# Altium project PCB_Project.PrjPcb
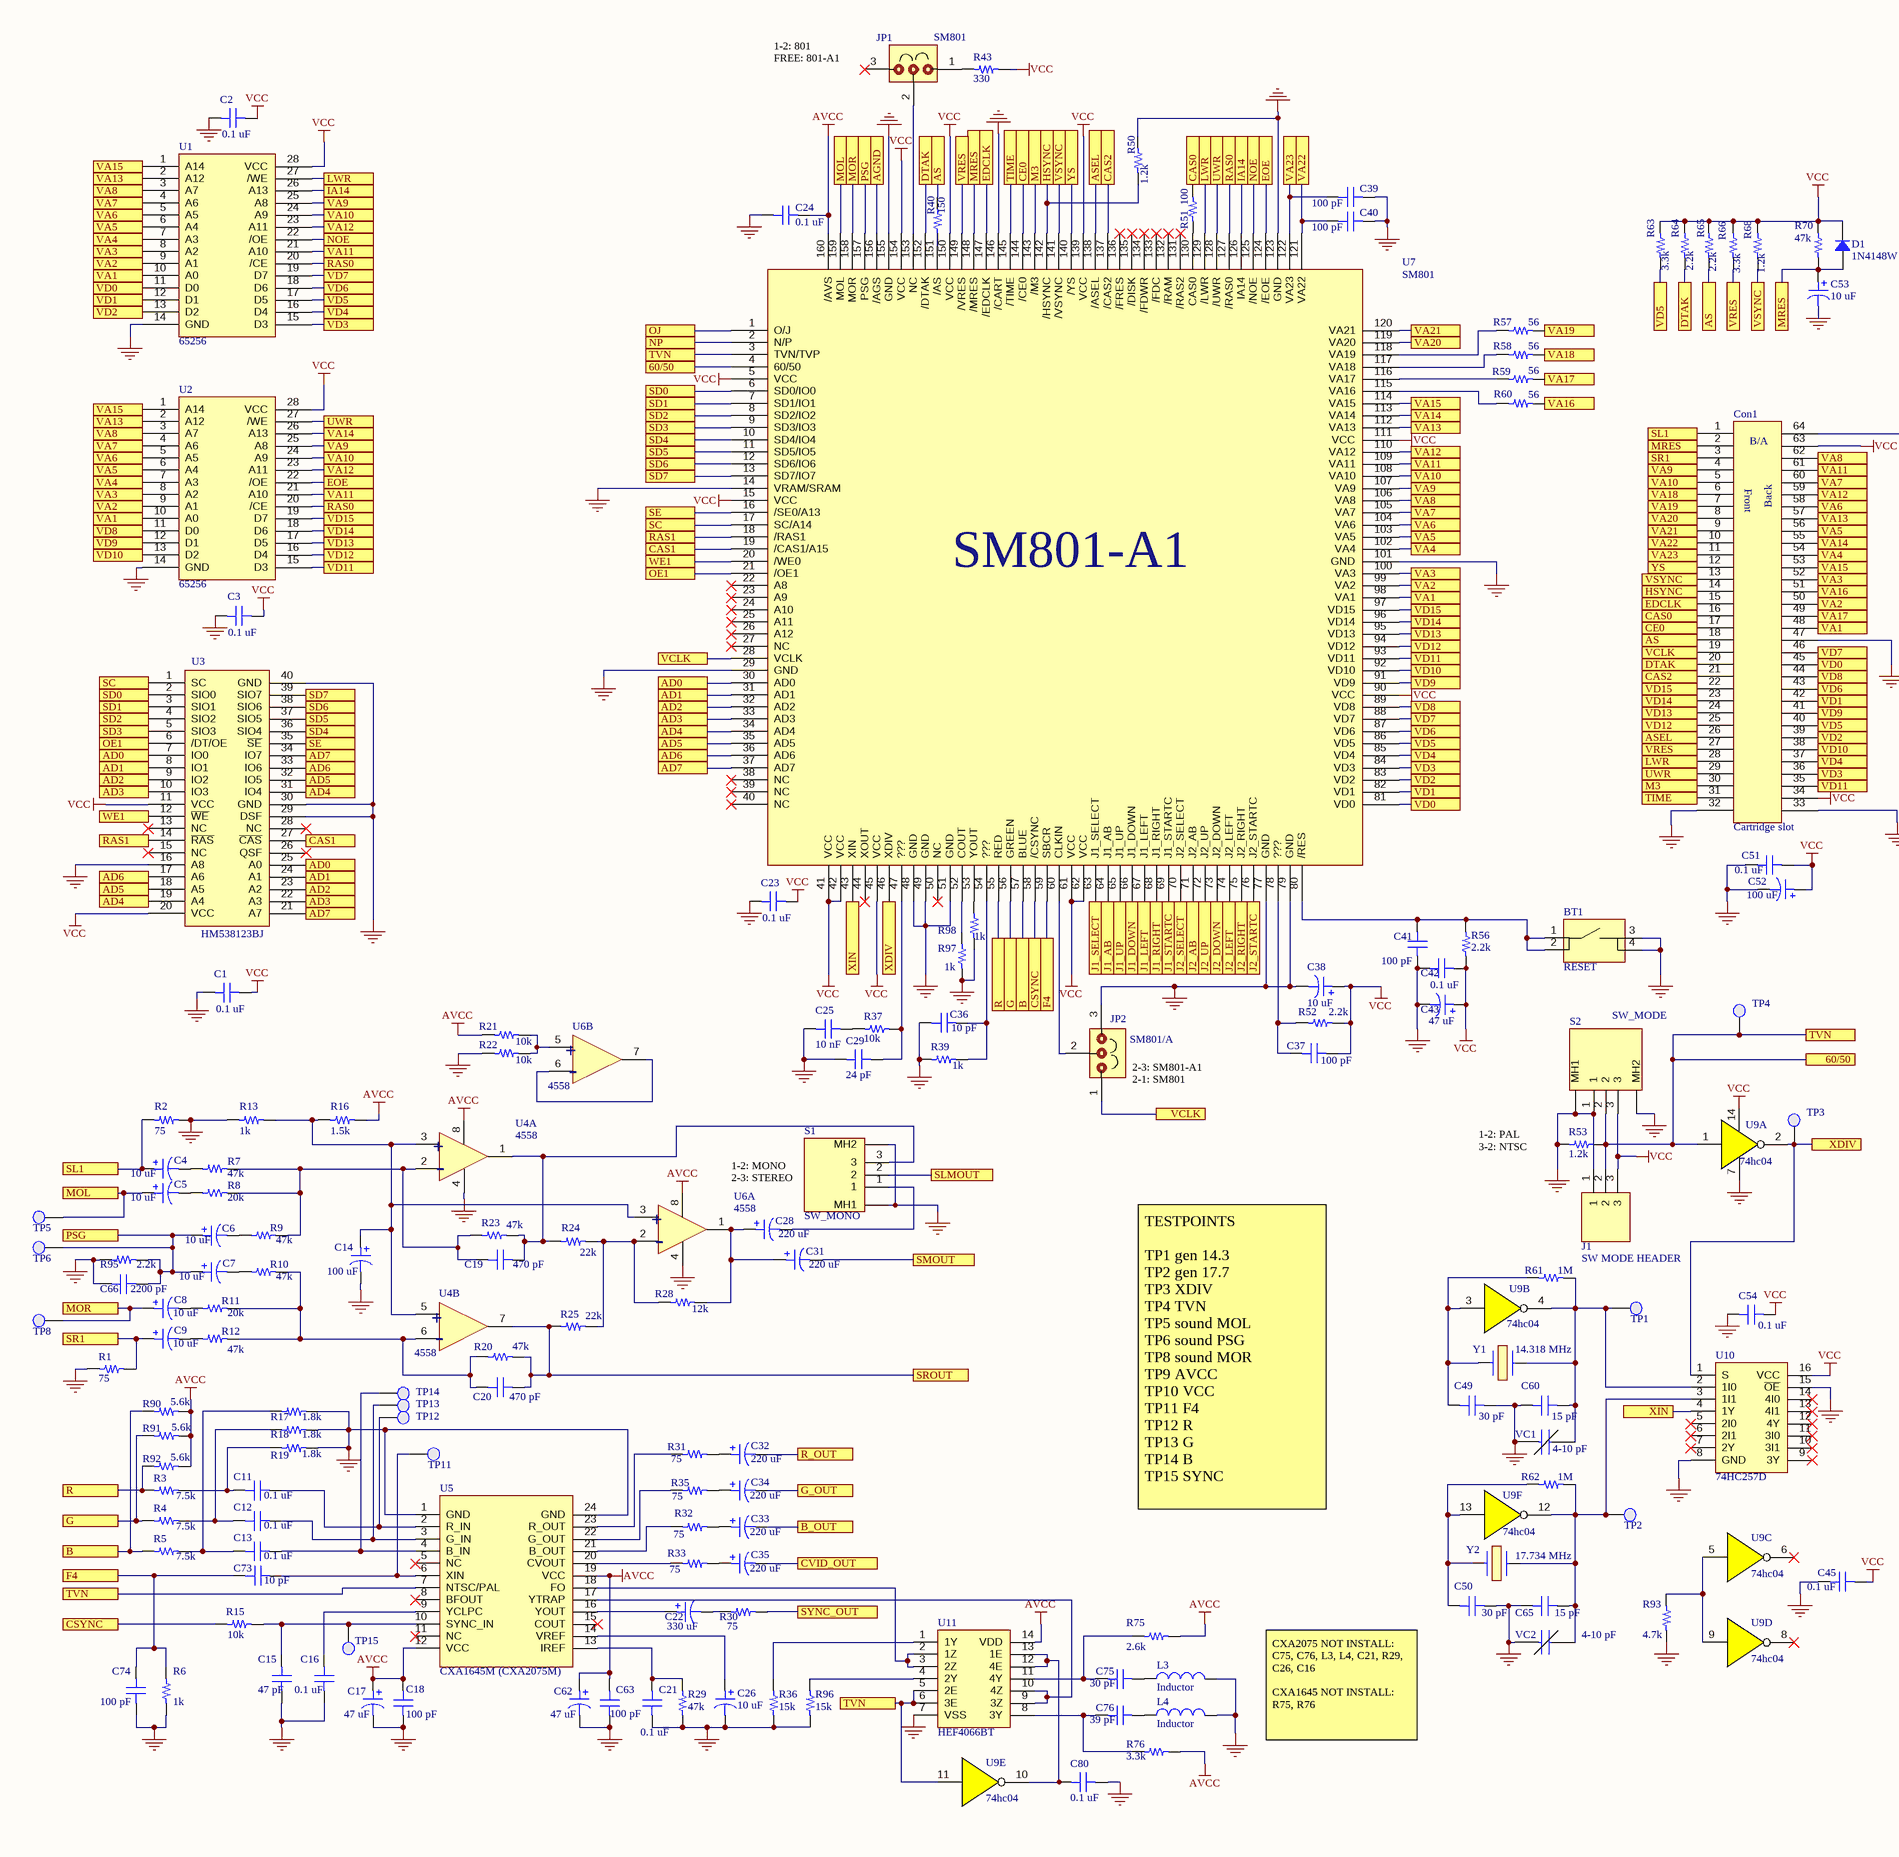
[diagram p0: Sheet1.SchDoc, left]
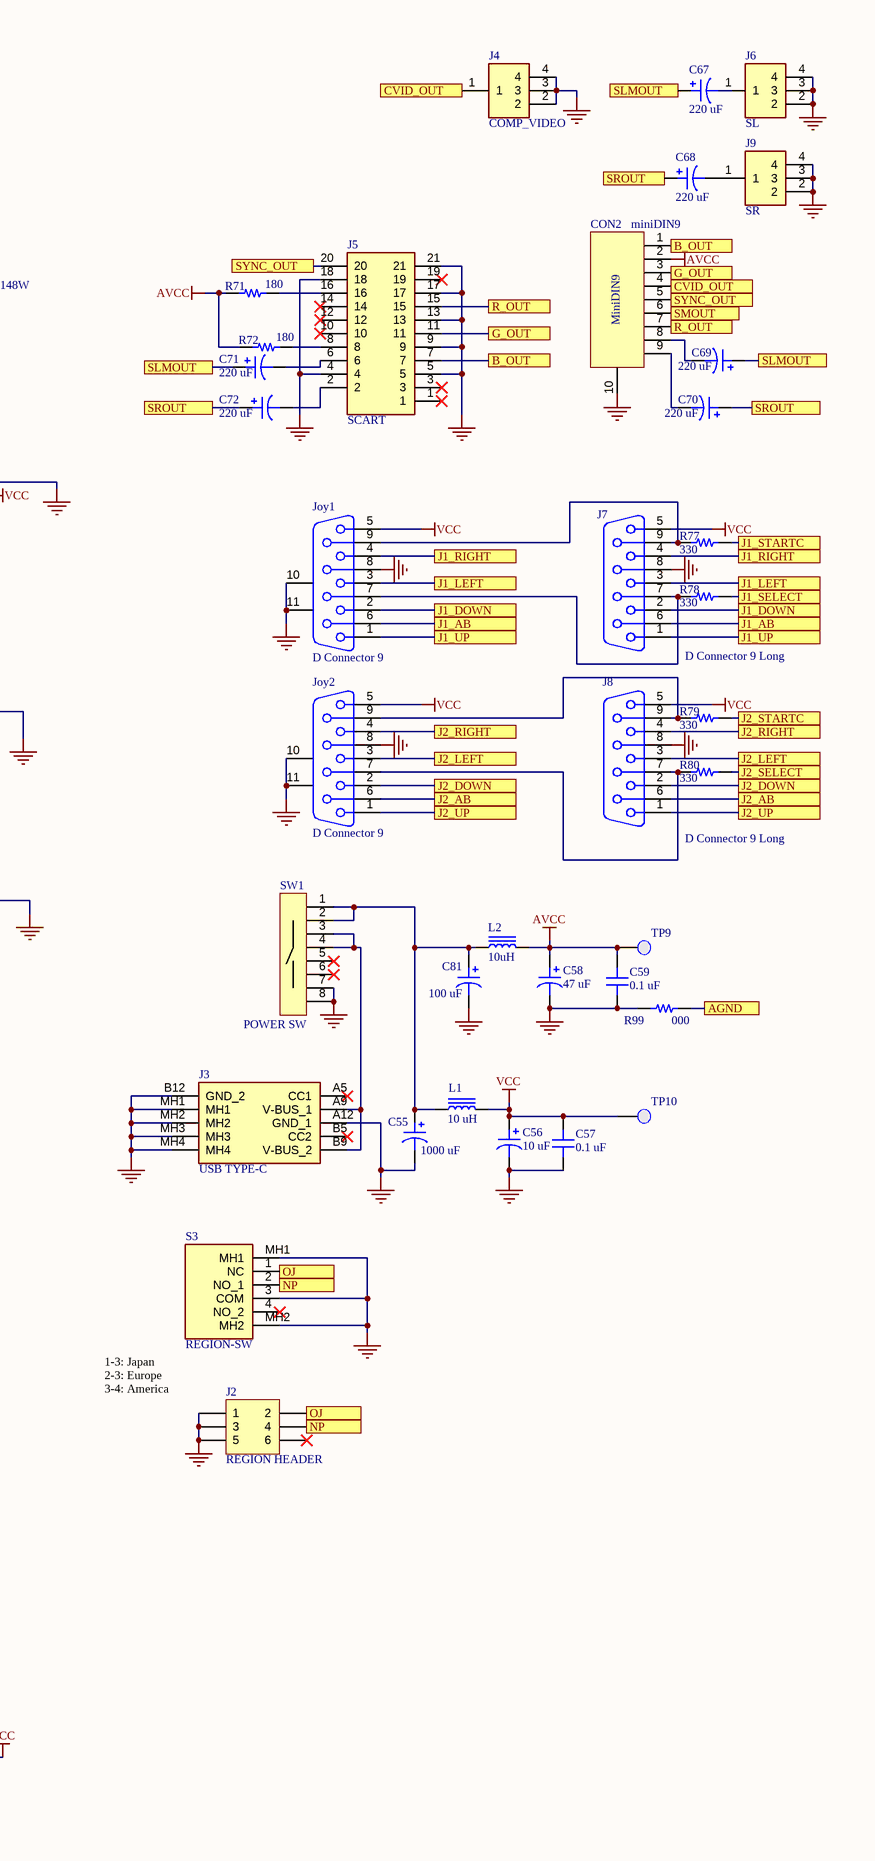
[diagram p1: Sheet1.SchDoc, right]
1 sheet, 192 parts. Net scope: flat (ports and power ports of the same name join across sheets).
Board file: SEGA_801_Remake.PcbDoc

## Sheet Sheet1.SchDoc: EHODRIVE - SM801 SEGA MD clone
size A2; DrawnBy: Hot pixel

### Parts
BT1  RESET  [KLS7-12]
C1  0.1 uF  [CAP 0805_2012]
C2  0.1 uF  [CAP 0805_2012]
C3  0.1 uF  [CAP 0805_2012]
C4  10 uF  [CAP TH ALUM ELEC D5.00mm S2.00mm H7.00mm]
C5  10 uF  [CAP TH ALUM ELEC D5.00mm S2.00mm H7.00mm]
C6  10 uF  [CAP TH ALUM ELEC D5.00mm S2.00mm H7.00mm]
C7  10 uF  [CAP TH ALUM ELEC D5.00mm S2.00mm H7.00mm]
C8  10 uF  [CAP TH ALUM ELEC D5.00mm S2.00mm H7.00mm]
C9  10 uF  [CAP TH ALUM ELEC D5.00mm S2.00mm H7.00mm]
C11  0.1 uF  [CAP 0805_2012]
C12  0.1 uF  [CAP 0805_2012]
C13  0.1 uF  [CAP 0805_2012]
C14  100 uF  [CAP TH ALUM ELEC D5.00mm S2.00mm H7.00mm]
C15  47 pF  [CAP 0805_2012]
C16  0.1 uF  [CAP 0805_2012]
C17  47 uF  [CAP TH ALUM ELEC D5.00mm S2.00mm H7.00mm]
C18  100 pF  [CAP 0805_2012]
C19  470 pF  [CAP 0805_2012]
C20  470 pF  [CAP 0805_2012]
C21  0.1 uF  [CAP 0805_2012]
C22  330 uF  [CAP TH ALUM ELEC D6.30mm S2.50mm H12.50mm]
C23  0.1 uF  [CAP 0805_2012]
C24  0.1 uF  [CAP 0805_2012]
C25  10 nF  [CAP 0805_2012]
C26  10 uF  [CAP TH ALUM ELEC D5.00mm S2.00mm H7.00mm]
C28  220 uF  [CAP TH ALUM ELEC D6.30mm S2.50mm H12.50mm]
C29  24 pF  [CAP 0805_2012]
C31  220 uF  [CAP TH ALUM ELEC D6.30mm S2.50mm H12.50mm]
C32  220 uF  [CAP TH ALUM ELEC D6.30mm S2.50mm H12.50mm]
C33  220 uF  [CAP TH ALUM ELEC D6.30mm S2.50mm H12.50mm]
C34  220 uF  [CAP TH ALUM ELEC D6.30mm S2.50mm H12.50mm]
C35  220 uF  [CAP TH ALUM ELEC D6.30mm S2.50mm H12.50mm]
C36  10 pF  [CAP 0805_2012]
C37  100 pF  [CAP 0805_2012]
C38  10 uF  [CAP TH ALUM ELEC D5.00mm S2.00mm H7.00mm]
C39  100 pF  [CAP 0805_2012]
C40  100 pF  [CAP 0805_2012]
C41  100 pF  [CAP 0805_2012]
C42  0.1 uF  [CAP 0805_2012]
C43  47 uF  [CAP TH ALUM ELEC D5.00mm S2.00mm H7.00mm]
C45  0.1 uF  [CAP 0805_2012]
C49  30 pF  [CAP 0805_2012]
C50  30 pF  [CAP 0805_2012]
C51  0.1 uF  [CAP 0805_2012]
C52  100 uF  [CAP TH ALUM ELEC D5.00mm S2.00mm H7.00mm]
C53  10 uF  [CAP TH ALUM ELEC D5.00mm S2.00mm H7.00mm]
C54  0.1 uF  [CAP 0805_2012]
C55  1000 uF  [CAP TH ALUM ELEC D6.30mm S2.50mm H12.50mm]
C56  10 uF  [CAP TH ALUM ELEC D5.00mm S2.00mm H7.00mm]
C57  0.1 uF  [CAP 0805_2012]
C58  47 uF  [CAP TH ALUM ELEC D6.30mm S2.50mm H12.50mm]
C59  0.1 uF  [CAP 0805_2012]
C60  15 pF  [CAP 0805_2012]
C62  47 uF  [CAP TH ALUM ELEC D5.00mm S2.00mm H7.00mm]
C63  100 pF  [CAP 0805_2012]
C65  15 pF  [CAP 0805_2012]
C66  2200 pF  [CAP 0805_2012]
C67  220 uF  [CAP TH ALUM ELEC D6.30mm S2.50mm H12.50mm]
C68  220 uF  [CAP TH ALUM ELEC D6.30mm S2.50mm H12.50mm]
C69  220 uF  [CAP TH ALUM ELEC D6.30mm S2.50mm H12.50mm]
C70  220 uF  [CAP TH ALUM ELEC D6.30mm S2.50mm H12.50mm]
C71  220 uF  [CAP TH ALUM ELEC D6.30mm S2.50mm H12.50mm]
C72  220 uF  [CAP TH ALUM ELEC D6.30mm S2.50mm H12.50mm]
C73  10 pF  [CAP 0805_2012]
C74  100 pF  [CAP 0805_2012]
C75  30 pF  [CAP 0805_2012]
C76  39 pF  [CAP 0805_2012]
C80  0.1 uF  [CAP 0805_2012]
C81  100 uF  [CAP TH ALUM ELEC D6.30mm S2.50mm H12.50mm]
Con1  Cartridge slot  [CARD_SLOT]
CON2  miniDIN9  [miniDIN9]
D1  1N4148W  [SOD-123]
J1  SW MODE HEADER  [8018700310012101]
J2  REGION HEADER  [HDR2X3]
J3  USB TYPE-C  [UJCHP3SMTTR]
J4  COMP_VIDEO  [1610390E]
J5  SCART  [PSG01601]
J6  SL  [1610390E]
J7  D Connector 9 Long  [DSUB1.385-2H9_LONG]
J8  D Connector 9 Long  [DSUB1.385-2H9_LONG]
J9  SR  [1610390E]
Joy1  D Connector 9  [DSUB1.385-2H9]
Joy2  D Connector 9  [DSUB1.385-2H9]
JP1  SM801  [JumperPad]
JP2  SM801/A  [JumperPad]
L1  10 uH  [BOURNS SRN8040]
L2  10uH  [TAIYO YUDEN NRS5030]
L3  Inductor  [Inductor vertical]
L4  Inductor  [Inductor vertical]
R1  75  [RES 0805_2012]
R2  75  [RES 0805_2012]
R3  7.5k  [RES 0805_2012]
R4  7.5k  [RES 0805_2012]
R5  7.5k  [RES 0805_2012]
R6  1k  [RES 0805_2012]
R7  47k  [RES 0805_2012]
R8  20k  [RES 0805_2012]
R9  47k  [RES 0805_2012]
R10  47k  [RES 0805_2012]
R11  20k  [RES 0805_2012]
R12  47k  [RES 0805_2012]
R13  1k  [RES 0805_2012]
R15  10k  [RES 0805_2012]
R16  1.5k  [RES 0805_2012]
R17  1.8k  [RES 0805_2012]
R18  1.8k  [RES 0805_2012]
R19  1.8k  [RES 0805_2012]
R20  47k  [RES 0805_2012]
R21  10k  [RES 0805_2012]
R22  10k  [RES 0805_2012]
R23  47k  [RES 0805_2012]
R24  22k  [RES 0805_2012]
R25  22k  [RES 0805_2012]
R28  value 12k  [RES 0805_2012]  (hidden comment: 22k)
R29  47k  [RES 0805_2012]
R30  75  [RES 0805_2012]
R31  75  [RES 0805_2012]
R32  75  [RES 0805_2012]
R33  75  [RES 0805_2012]
R35  75  [RES 0805_2012]
R36  15k  [RES 0805_2012]
R37  10k  [RES 0805_2012]
R39  1k  [RES 0805_2012]
R40  150  [RES 0805_2012]
R43  330  [RES 0805_2012]
R50  1.2k  [RES 0805_2012]
R51  100  [RES 0805_2012]
R52  2.2k  [RES 0805_2012]
R53  1.2k  [RES 0805_2012]
R56  2.2k  [RES 0805_2012]
R57  56  [RES 0805_2012]
R58  56  [RES 0805_2012]
R59  56  [RES 0805_2012]
R60  56  [RES 0805_2012]
R61  1M  [RES 0805_2012]
R62  1M  [RES 0805_2012]
R63  3.3k  [RES 0805_2012]
R64  2.2k  [RES 0805_2012]
R65  2.2k  [RES 0805_2012]
R66  3.3k  [RES 0805_2012]
R68  1.2k  [RES 0805_2012]
R70  47k  [RES 0805_2012]
R71  180  [RES 0805_2012]
R72  180  [RES 0805_2012]
R75  2.6k  [RES 0805_2012]
R76  3.3k  [RES 0805_2012]
R77  330  [RES 0805_2012]
R78  330  [RES 0805_2012]
R79  330  [RES 0805_2012]
R80  330  [RES 0805_2012]
R90  5.6k  [RES 0805_2012]
R91  5.6k  [RES 0805_2012]
R92  5.6k  [RES 0805_2012]
R93  4.7k  [RES 0805_2012]
R95  2.2k  [RES 0805_2012]
R96  15k  [RES 0805_2012]
R97  1k  [RES 0805_2012]
R98  1k  [RES 0805_2012]
R99  000  [RES 0805_2012]
S1  SW_MONO  [SS12D07VG4NSGAPA]
S2  SW_MODE  [SS12D07VG4NSGAPA]
S3  REGION-SW  [SK13D08G5E]
SW1  POWER SW  [SW_6_4]
TP1  Test point  [TP]  (value not drawn)
TP2  Test point  [TP]  (value not drawn)
TP3  Test point  [TP]  (value not drawn)
TP4  Test point  [TP]  (value not drawn)
TP5  Test point  [TP]  (value not drawn)
TP6  Test point  [TP]  (value not drawn)
TP8  Test point  [TP]  (value not drawn)
TP9  Test point  [TP]  (value not drawn)
TP10  Test point  [TP]  (value not drawn)
TP11  Test point  [TP]  (value not drawn)
TP12  Test point  [TP]  (value not drawn)
TP13  Test point  [TP]  (value not drawn)
TP14  Test point  [TP]  (value not drawn)
TP15  Test point  [TP]  (value not drawn)
U1  65256  [SOP28]
U2  65256  [SOP28]
U3  HM538123BJ  [SOP40]
U4  4558  [SOIC127P600X175-8N]  (parts A,B of 2)
U5  CXA1645M (CXA2075M)  [SOP24N]
U6  4558  [SOIC127P600X175-8N]  (parts A,B of 2)
U7  SM801  [SM801-A1]
U9  74hc04  [SOIC127P600X175-14N]  (parts A,B,C,D,E,F of 6)
U10  74HC257D  [74HC257D652]
U11  HEF4066BT  [SOIC127P600X175-14N]
VC1  4-10 pF  [CAPPM5040X320N]
VC2  4-10 pF  [CAPPM5040X320N]
Y1  14.318 MHz  [12000MHzHC494H3050408518pFATF]
Y2  17.734 MHz  [12000MHzHC494H3050408518pFATF]

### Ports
60/50, AD0, AD1, AD2, AD3, AD4, AD5, AD6, AD7, AGND, AS, ASEL, B, B_OUT, CAS0, CAS1, CAS2, CE0, CSYNC, CVID_OUT, DTAK, EDCLK, EOE, F4, G, G_OUT, HSYNC, IA14, J1_AB, J1_DOWN, J1_LEFT, J1_RIGHT, J1_SELECT, J1_STARTC, J1_UP, J2_AB, J2_DOWN, J2_LEFT, J2_RIGHT, J2_SELECT, J2_STARTC, J2_UP, LWR, M3, MOL, MOR, MRES, NOE, NP, OE1, OJ, PSG, R, R_OUT, RAS0, RAS1, SC, SD0, SD1, SD2, SD3, SD4, SD5, SD6, SD7, SE, SL1, SLMOUT, SMOUT, SR1, SROUT, SYNC_OUT, TIME, TVN, UWR, VA1, VA2, VA3, VA4, VA5, VA6, VA7, VA8, VA9, VA10, VA11, VA12, VA13, VA14, VA15, VA16, VA17, VA18, VA19, VA20, VA21, VA22, VA23, VCLK, VD0, VD1, VD2, VD3, VD4, VD5, VD6, VD7, VD8, VD9, VD10, VD11, VD12, VD13, VD14, VD15, VRES, VSYNC, WE1, XDIV, XIN, YS

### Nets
AVCC: C17.1 C18.1 C24.1 C58.1 C59.1 C62.1 C63.1 CON2.2 L2.2 R16.2 R21.1 R71.1 R72.1 R75.2 R76.2 R90.1 R91.1 R92.1 TP9.1 U4.8 U5.12(VCC) U5.19(VCC) U6.8 U7.160(/AVS) U11.14(VDD)
GND: BT1.3 BT1.4 C1.2 C2.2 C3.2 C14.2 C15.2 C16.2 C17.2 C18.2 C21.2 C23.2 C24.2 C25.2 C26.2 C29.2 C36.2 C38.2 C39.1 C40.1 C41.1 C42.2 C43.2 C45.2 C49.1 C50.1 C51.2 C52.2 C53.2 C54.2 C55.2 C56.2 C57.2 C58.2 C59.2 C60.2 C62.2 C63.2 C65.2 C66.2 C74.2 C80.1 C81.2 Con1.32(Ain) Con1.33 Con1.47 Con1.64 CON2.10 J1.1 J2.1 J2.3 J2.5 J3.A12(GND_1) J3.B12(GND_2) J3.MH1 J3.MH2 J3.MH3 J3.MH4 J4.2 J4.3 J4.4 J5.4 J5.5 J5.9 J5.13 J5.17 J5.18 J5.21 J6.2 J6.3 J6.4 J7.8 J8.8 J9.2 J9.3 J9.4 Joy1.8 Joy1.10(MH1) Joy1.11(MH2) Joy2.8 Joy2.10(MH1) Joy2.11(MH2) JP2.3 L3.2 L4.2 R1.2 R2.1 R6.2 R13.1 R17.2 R18.2 R19.2 R22.1 R29.2 R36.1 R39.2 R50.2 R53.2 R93.1 R95.1 R96.1 R97.2 R98.2 R99.2 S1.MH1 S1.MH2 S2.1 S2.MH1 S2.MH2 S3.3(COM) S3.MH1 S3.MH2 SW1.7 SW1.8 U1.14(GND) U2.14(GND) U3.16(A8) U3.29(DSF) U3.30(GND) U3.40(GND) U4.4 U5.1(GND) U5.24(GND) U6.4 U7.14(VRAM/SRAM) U7.29(GND) U7.48(GND) U7.49(GND) U7.51(GND) U7.77(GND) U7.79(GND) U7.101(GND) U7.123(GND) U7.146(/CART) U7.155(GND) U9.7(gnd) U10.8(GND) U10.15(~{OE}) U11.7(VSS) VC1.1(+) VC2.1(+)
VCC: C1.1 C2.1 C3.1 C23.1 C37.1 C38.1 C42.1 C43.1 C45.1 C51.1 C52.1 C54.1 C56.1 C57.1 Con1.34 Con1.63 D1.2 J1.3 J7.5 J8.5 Joy1.5 Joy2.5 L1.2 R43.2 R52.2 R56.1 R63.2 R64.2 R65.2 R66.2 R68.2 R70.2 S2.3 TP10.1 U1.28(VCC) U2.28(VCC) U3.11(VCC) U3.20(VCC) U7.5(VCC) U7.15(VCC) U7.41(VCC) U7.42(VCC) U7.45(VCC) U7.61(VCC) U7.62(VCC) U7.90(VCC) U7.111(VCC) U7.139(VCC) U7.150(VCC) U7.154(VCC) U9.14(vcc) U10.16(VCC)
NetBT1_1: BT1.1 BT1.2 C41.2 R56.2 U7.80(/RES)
NetC4_1: C4.1 Con1.1(Ain) R2.2 ; port SL1
NetC4_2: C4.2 R7.1
NetC5_1: C5.1 TP5.1 U7.159(MOL) ; port MOL
NetC5_2: C5.2 R8.1
NetC6_1: C6.1 C7.1 C66.1 R95.2 TP6.1 U7.157(PSG) ; port PSG
NetC6_2: C6.2 R9.1
NetC7_2: C7.2 R10.1
NetC8_1: C8.1 TP8.1 U7.158(MOR) ; port MOR
NetC8_2: C8.2 R11.1
NetC9_1: C9.1 Con1.3(Ain) R1.1 ; port SR1
NetC9_2: C9.2 R12.1
NetC11_1: C11.1 TP12.1 U5.2(R_IN)
NetC11_2: C11.2 R3.1 R19.1
NetC12_1: C12.1 TP13.1 U5.3(G_IN)
NetC12_2: C12.2 R4.1 R18.1
NetC13_1: C13.1 TP14.1 U5.4(B_IN)
NetC13_2: C13.2 R5.1 R17.1
NetC14_1: C14.1 R13.2 R16.1 U4.3 U4.5 U6.3
NetC15_1: C15.1 R15.1 TP15.1 U5.10(SYNC_IN)
NetC16_1: C16.1 U5.9(YCLPC)
NetC19_1: C19.1 R23.2 R24.1 S1.3 U4.1
NetC19_2: C19.2 R7.2 R8.2 R9.2 R23.1 U4.2(-)
NetC20_1: C20.1 C68.1 C70.1 C72.1 R20.2 R25.1 U4.7 ; port SROUT
NetC20_2: C20.2 R10.2 R11.2 R12.2 R20.1 U4.6(-)
NetC21_1: C21.1 R29.1 U5.13(IREF)
NetC22_1: C22.1 U5.16(YOUT)
NetC22_2: C22.2 R30.1
NetC25_1: C25.1 R37.2
NetC26_1: C26.1 U5.14(VREF)
NetC28_1: C28.1 C31.1 R28.2 U6.1
NetC28_2: C28.2 S1.1
NetC29_1: C29.1 R37.1 U7.47(???)
NetC31_2: C31.2 CON2.6 ; port SMOUT
NetC32_1: C32.1 R31.2
NetC32_2: C32.2 CON2.7 J5.15 ; port R_OUT
NetC33_1: C33.1 R32.2
NetC33_2: C33.2 CON2.1 J5.7 ; port B_OUT
NetC34_1: C34.1 R35.2
NetC34_2: C34.2 CON2.3 J5.11 ; port G_OUT
NetC35_1: C35.1 R33.2
NetC35_2: C35.2 CON2.4 J4.1 ; port CVID_OUT
NetC36_1: C36.1 R39.1 U7.54(???)
NetC37_2: C37.2 R52.1 U7.78(???)
NetC39_2: C39.2 Con1.11(Ain) U7.122(VA23) ; port VA23
NetC40_2: C40.2 Con1.10(Ain) U7.121(VA22) ; port VA22
NetC49_2: C49.2 R61.2 U9.3 Y1.2(CRYSTAL_2)
NetC50_2: C50.2 R62.2 U9.13 Y2.2(CRYSTAL_2)
NetC53_1: C53.1 Con1.2(Ain) D1.1 R70.1 U7.148(/MRES) ; port MRES
NetC55_1: C55.1 C81.1 L1.1 L2.1 SW1.1 SW1.2
NetC60_1: C60.1 R61.1 TP1.1 U9.4 U10.2(1I0) VC1.2(-) Y1.1(CRYSTAL_1)
NetC65_1: C65.1 R62.1 TP2.1 U9.12 U10.3(1I1) VC2.2(-) Y2.1(CRYSTAL_1)
NetC67_1: C67.1 C69.1 C71.1 S1.2 ; port SLMOUT
NetC67_2: C67.2 J6.1
NetC68_2: C68.2 J9.1
NetC69_2: C69.2 CON2.8
NetC70_2: C70.2 CON2.9
NetC71_2: C71.2 J5.6
NetC72_2: C72.2 J5.2
NetC73_1: C73.1 C74.1 R6.1 U7.59(SBCR) ; port F4
NetC73_2: C73.2 TP11.1 U5.6(XIN)
NetC75_1: C75.1 R75.1 U11.11(4Y)
NetC75_2: C75.2 L3.1
NetC76_1: C76.1 R76.1 U11.8(3Y)
NetC76_2: C76.2 L4.1
NetC80_2: C80.2 U9.10 U11.12(4E) U11.13(1E)
NetCon1_4: Con1.4(Ain) U1.25(A8) U2.25(A8) U7.107(VA9) ; port VA9
NetCon1_5: Con1.5(Ain) U1.24(A9) U2.24(A9) U7.108(VA10) ; port VA10
NetCon1_6: Con1.6(Ain) R58.2 ; port VA18
NetCon1_7: Con1.7(Ain) R57.2 ; port VA19
NetCon1_8: Con1.8(Ain) U7.119(VA20) ; port VA20
NetCon1_9: Con1.9(Ain) U7.120(VA21) ; port VA21
NetCon1_12: Con1.12(Ain) U7.140(/YS) ; port YS
NetCon1_13: Con1.13(Ain) R68.1 U7.141(/VSYNC) ; port VSYNC
NetCon1_14: Con1.14(Ain) R50.1 U7.142(/HSYNC) ; port HSYNC
NetCon1_15: Con1.15(Ain) U7.147(/EDCLK) ; port EDCLK
NetCon1_16: Con1.16(Ain) R51.2 ; port CAS0
NetCon1_17: Con1.17(Ain) U7.144(/CE0) ; port CE0
NetCon1_18: Con1.18(Ain) R40.2 R65.1 ; port AS
NetCon1_19: Con1.19(Ain) JP2.1 U7.28(VCLK) ; port VCLK
NetCon1_20: Con1.20(Ain) R64.1 U7.152(/DTAK) ; port DTAK
NetCon1_21: Con1.21(Ain) U7.137(/CAS2) ; port CAS2
NetCon1_22: Con1.22(Ain) U2.19(D7) U7.97(VD15) ; port VD15
NetCon1_23: Con1.23(Ain) U2.18(D6) U7.96(VD14) ; port VD14
NetCon1_24: Con1.24(Ain) U2.17(D5) U7.95(VD13) ; port VD13
NetCon1_25: Con1.25(Ain) U2.16(D4) U7.94(VD12) ; port VD12
NetCon1_26: Con1.26(Ain) U7.138(/ASEL) ; port ASEL
NetCon1_27: Con1.27(Ain) R66.1 U7.149(/VRES) ; port VRES
NetCon1_28: Con1.28(Ain) U1.27(/WE) U7.129(/LWR) ; port LWR
NetCon1_29: Con1.29(Ain) U2.27(/WE) U7.128(/UWR) ; port UWR
NetCon1_30: Con1.30(Ain) U7.143(/M3) ; port M3
NetCon1_31: Con1.31(Ain) U7.145(/TIME) ; port TIME
NetCon1_35: Con1.35 U2.15(D3) U7.93(VD11) ; port VD11
NetCon1_36: Con1.36 U1.15(D3) U7.84(VD3) ; port VD3
NetCon1_37: Con1.37 U1.16(D4) U7.85(VD4) ; port VD4
NetCon1_38: Con1.38 U2.13(D2) U7.92(VD10) ; port VD10
NetCon1_39: Con1.39 U1.13(D2) U7.83(VD2) ; port VD2
NetCon1_40: Con1.40 R63.1 U1.17(D5) U7.86(VD5) ; port VD5
NetCon1_41: Con1.41 U2.12(D1) U7.91(VD9) ; port VD9
NetCon1_42: Con1.42 U1.12(D1) U7.82(VD1) ; port VD1
NetCon1_43: Con1.43 U1.18(D6) U7.87(VD6) ; port VD6
NetCon1_44: Con1.44 U2.11(D0) U7.89(VD8) ; port VD8
NetCon1_45: Con1.45 U1.11(D0) U7.81(VD0) ; port VD0
NetCon1_46: Con1.46 U1.19(D7) U7.88(VD7) ; port VD7
NetCon1_48: Con1.48 U1.10(A0) U2.10(A0) U7.98(VA1) ; port VA1
NetCon1_49: Con1.49 R59.2 ; port VA17
NetCon1_50: Con1.50 U1.9(A1) U2.9(A1) U7.99(VA2) ; port VA2
NetCon1_51: Con1.51 R60.2 ; port VA16
NetCon1_52: Con1.52 U1.8(A2) U2.8(A2) U7.100(VA3) ; port VA3
NetCon1_53: Con1.53 U1.1(A14) U2.1(A14) U7.114(VA15) ; port VA15
NetCon1_54: Con1.54 U1.7(A3) U2.7(A3) U7.102(VA4) ; port VA4
NetCon1_55: Con1.55 U2.26(A13) U7.113(VA14) ; port VA14
NetCon1_56: Con1.56 U1.6(A4) U2.6(A4) U7.103(VA5) ; port VA5
NetCon1_57: Con1.57 U1.2(A12) U2.2(A12) U7.112(VA13) ; port VA13
NetCon1_58: Con1.58 U1.5(A5) U2.5(A5) U7.104(VA6) ; port VA6
NetCon1_59: Con1.59 U1.23(A11) U2.23(A11) U7.110(VA12) ; port VA12
NetCon1_60: Con1.60 U1.4(A6) U2.4(A6) U7.105(VA7) ; port VA7
NetCon1_61: Con1.61 U1.21(A10) U2.21(A10) U7.109(VA11) ; port VA11
NetCon1_62: Con1.62 U1.3(A7) U2.3(A7) U7.106(VA8) ; port VA8
NetCON2_5: CON2.5 J5.20 R30.2 ; port SYNC_OUT
NetJ1_2: J1.2 R53.1 S2.2 TP4.1 U5.7(NTSC/PAL) U7.3(TVN/TVP) U7.4(60/50) U9.1 U9.11 U11.5(2E) U11.6(3E) ; port 60/50, port TVN
NetJ2_2: J2.2 S3.1(NC) U7.1(O/J) ; port OJ
NetJ2_4: J2.4 S3.2(NO_1) U7.2(N/P) ; port NP
NetJ3_A9: J3.A9(V-BUS_1) J3.B9(V-BUS_2) SW1.3 SW1.4
NetJ5_8: J5.8 R72.2
NetJ5_16: J5.16 R71.2
NetJ7_1: J7.1 Joy1.1 U7.65(J1_UP) ; port J1_UP
NetJ7_2: J7.2 Joy1.2 U7.66(J1_DOWN) ; port J1_DOWN
NetJ7_3: J7.3 Joy1.3 U7.67(J1_LEFT) ; port J1_LEFT
NetJ7_4: J7.4 Joy1.4 U7.68(J1_RIGHT) ; port J1_RIGHT
NetJ7_6: J7.6 Joy1.6 U7.64(J1_AB) ; port J1_AB
NetJ7_7: J7.7 Joy1.7 R78.1
NetJ7_9: J7.9 Joy1.9 R77.1
NetJ8_1: J8.1 Joy2.1 U7.72(J2_UP) ; port J2_UP
NetJ8_2: J8.2 Joy2.2 U7.73(J2_DOWN) ; port J2_DOWN
NetJ8_3: J8.3 Joy2.3 U7.74(J2_LEFT) ; port J2_LEFT
NetJ8_4: J8.4 Joy2.4 U7.75(J2_RIGHT) ; port J2_RIGHT
NetJ8_6: J8.6 Joy2.6 U7.71(J2_AB) ; port J2_AB
NetJ8_7: J8.7 Joy2.7 R80.1
NetJ8_9: J8.9 Joy2.9 R79.1
NetJP1_1: JP1.1 R43.1
NetJP1_2: JP1.2 U7.153(NC)
NetJP2_2: JP2.2 U7.60(CLKIN)
NetR3_2: R3.2 R92.2 U7.55(RED) ; port R
NetR4_2: R4.2 R91.2 U7.56(GREEN) ; port G
NetR5_2: R5.2 R90.2 U7.57(BLUE) ; port B
NetR15_2: R15.2 U7.58(/CSYNC) ; port CSYNC
NetR21_2: R21.2 R22.2 U6.5
NetR24_2: R24.2 R25.2 R28.1 U6.2(-)
NetR31_1: R31.1 U5.23(R_OUT)
NetR32_1: R32.1 U5.21(B_OUT)
NetR33_1: R33.1 U5.20(CVOUT)
NetR35_1: R35.1 U5.22(G_OUT)
NetR36_2: R36.2 U11.1(1Y)
NetR40_1: R40.1 U7.151(/AS)
NetR51_1: R51.1 U7.130(CAS0)
NetR57_1: R57.1 U7.118(VA19)
NetR58_1: R58.1 U7.117(VA18)
NetR59_1: R59.1 U7.116(VA17)
NetR60_1: R60.1 U7.115(VA16)
NetR77_2: R77.2 U7.69(J1_STARTC) ; port J1_STARTC
NetR78_2: R78.2 U7.63(J1_SELECT) ; port J1_SELECT
NetR79_2: R79.2 U7.76(J2_STARTC) ; port J2_STARTC
NetR80_2: R80.2 U7.70(J2_SELECT) ; port J2_SELECT
NetR93_2: R93.2 U9.5 U9.9
NetR96_2: R96.2 U11.4(2Y)
NetR97_1: R97.1 U7.52(COUT)
NetR98_1: R98.1 U7.53(YOUT)
NetR99_1: R99.1 U7.156(/AGS) ; port AGND
NetTP3_1: TP3.1 U7.46(XDIV) U9.2 U10.1(S) ; port XDIV
NetU1_20: U1.20(/CE) U2.20(/CE) U7.127(/RAS0) ; port RAS0
NetU1_22: U1.22(/OE) U7.125(/NOE) ; port NOE
NetU1_26: U1.26(A13) U7.126(IA14) ; port IA14
NetU2_22: U2.22(/OE) U7.124(/EOE) ; port EOE
NetU3_1: U3.1(SC) U7.17(SC/A14) ; port SC
NetU3_2: U3.2(SIO0) U7.6(SD0/IO0) ; port SD0
NetU3_3: U3.3(SIO1) U7.7(SD1/IO1) ; port SD1
NetU3_4: U3.4(SIO2) U7.8(SD2/IO2) ; port SD2
NetU3_5: U3.5(SIO3) U7.9(SD3/IO3) ; port SD3
NetU3_6: U3.6(/DT/OE) U7.21(/OE1) ; port OE1
NetU3_7: U3.7(IO0) U3.25(A0) U7.30(AD0) ; port AD0
NetU3_8: U3.8(IO1) U3.24(A1) U7.31(AD1) ; port AD1
NetU3_9: U3.9(IO2) U3.23(A2) U7.32(AD2) ; port AD2
NetU3_10: U3.10(IO3) U3.22(A3) U7.33(AD3) ; port AD3
NetU3_12: U3.12(~{W}~{E}) U7.20(/WE0) ; port WE1
NetU3_14: U3.14(~{R}~{A}~{S}) U7.18(/RAS1) ; port RAS1
NetU3_17: U3.17(A6) U3.33(IO6) U7.36(AD6) ; port AD6
NetU3_18: U3.18(A5) U3.32(IO5) U7.35(AD5) ; port AD5
NetU3_19: U3.19(A4) U3.31(IO4) U7.34(AD4) ; port AD4
NetU3_21: U3.21(A7) U3.34(IO7) U7.37(AD7) ; port AD7
NetU3_27: U3.27(~{C}~{A}~{S}) U7.19(/CAS1/A15) ; port CAS1
NetU3_35: U3.35(~{S}~{E}) U7.16(/SE0/A13) ; port SE
NetU3_36: U3.36(SIO4) U7.10(SD4/IO4) ; port SD4
NetU3_37: U3.37(SIO5) U7.11(SD5/IO5) ; port SD5
NetU3_38: U3.38(SIO6) U7.12(SD6/IO6) ; port SD6
NetU3_39: U3.39(SIO7) U7.13(SD7/IO7) ; port SD7
NetU5_17: U5.17(YTRAP) U11.9(3Z) U11.10(4Z)
NetU5_18: U5.18(FO) U11.2(1Z) U11.3(2Z)
NetU6_6: U6.6(-) U6.7
NetU7_43: U7.43(XIN) U10.4(1Y) ; port XIN

Not connected (* = marked no-connect by the designer): J2 6*; J3 A5(CC1)* B5(CC2)*; J5 1* 3* 10* 12* 14* 19*; JP1 3(17)*; S3 4(NO_2)*; SW1 5(10)* 6(11)*; U3 13(NC)* 15(NC)* 26(QSF)* 28(NC)*; U5 5(NC)* 8(BFOUT)* 11(NC)* 15(COUT)*; U7 22(A8)* 23(A9)* 24(A10)* 25(A11)* 26(A12)* 27(NC)* 38(NC)* 39(NC)* 40(NC)* 44(XOUT)* 50(NC)* 131(/RAS2)* 132(/RAM)* 133(/FDC)* 134(/FDWR)* 135(/DISK)* 136(/FRES)*; U9 6(46)* 8(46)*; U10 5(2I0)* 6(2I1)* 7(2Y)* 9(3Y)* 10(3I1)* 11(3I0)* 12(4Y)* 13(4I1)* 14(4I0)*

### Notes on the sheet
- (near JP1) 1-2: 801
  FREE: 801-A1
- (near JP2) 2-3: SM801-A1
  2-1: SM801
- 1-2: PAL
  3-2: NTSC
- 1-2: MONO
  2-3: STEREO
- (near J2) 1-3: Japan
  2-3: Europe
  3-4: America
- TESTPOINTS
  TP1	gen 14.3
  TP2	gen 17.7
  TP3	XDIV
  TP4	TVN
  TP5	sound MOL
  TP6	sound PSG
  TP8	sound MOR
  TP9	AVCC
  TP10	VCC
  TP11	F4
  TP12	R
  TP13	G
  TP14	B
  TP15	SYNC
- CXA2075 NOT INSTALL:
  C75, C76, L3, L4, C21, R29, C26, C16
  CXA1645 NOT INSTALL:
  R75, R76

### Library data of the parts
BT1 = KLKLS7-TS1202: KLS7-TS1202
C1-C3 C11-C13 C15 C16 C18-C21 C23-C25 C29 C36 C37 C39-C42 C45 C49-C51 C54 C57 C59 C60 C63 C65 C66 C73-C76 C80 = CBR08C160JAGAC: CAP CER 16PF 250V C0G/NP0 0805; manufacturer: KEMET; Temperature Coefficient: C0G, NP0; Tolerance: ±5%
C4-C9 C14 C17 C26 C38 C43 C52 C53 C56 C62 = ECE-A1AKA470: CAP ALUM 47UF 20% 10V RADIAL; manufacturer: Panasonic Electronic Components; Capacitance: 47µF; Lifetime @ Temp.: 1000 Hrs @ 85°C; Polarization: Polar; Ripple Current @ High Frequency: 110.5mA @ 10kHz; value: 47µF
C22 C28 C31-C35 C55 C58 C67-C72 C81 = 80ZLH33MEFC6.3X11: CAP ALUM 33UF 20% 80V RADIAL; manufacturer: Rubycon; Capacitance: 33µF; Lifetime @ Temp.: 6000 Hrs @ 105°C; Polarization: Polar; value: 33µF; Impedance: 570 mOhms; Ripple Current @ Low Frequency: 112.14mA @ 120Hz
Con1 = CARD_SLOT
CON2 = DIN9
D1 = 1N4148W-E3-08: DIODE GEN PURP 75V 150MA SOD123; Manufacturer: Vishay Semiconductor Diodes Division; Current - Reverse Leakage @ Vr: 100µA @ 100V; Diode Type: Standard; Reverse Recovery Time (trr): 4ns; Speed: Small Signal =< 200mA (Io), Any Speed; Voltage - Forward (Vf) (Max) @ If: 1.2V @ 100mA
J1 = 801-87-003-10-012101: Connector; Manufacturer_Name: Preci-Dip
J2 = Header 3X2: Header, 3-Pin, Dual row
J3 = UJC-HP-3-SMT-TR: Connector; Manufacturer_Name: CUI Inc.
J4 J6 J9 = 161-0390-E: Connector; Manufacturer_Name: Kobiconn
J5 = SCART: Connector; Manufacturer_Name: PRO SIGNAL
J7 J8 = D Connector 9 Long: Receptacle Assembly, 9 Position, Right Angle; PackageDocument: O; Positions: 9
Joy1 Joy2 = D Connector 9: Receptacle Assembly, 9 Position, Right Angle; PackageDocument: O; Positions: 9
JP1 JP2 = JumperPad
L1 = SRN8040-1R5Y: FIXED IND 1.5UH 7A 11 MOHM SMD; Manufacturer: Bourns Inc.; Current - Saturation: 8.2A; DC Resistance (DCR): 11mOhm Max; Frequency - Self Resonant: 55MHz; Inductance: 1.5 µH; Inductance Frequency - Test: 100 kHz; Material - Core: Ferrite; Q @ Freq: 13 @ 7.96MHz; Shielding: Semi-Shielded; Tolerance: ±30%; Type: Drum Core, Wirewound; Value: 1.5 µH
L2 = NRS5030T330MMGJV: FIXED IND 33UH 800MA 292.5 MOHM; Manufacturer: Taiyo Yuden; Current - Saturation: 1.15A; DC Resistance (DCR): 292.5mOhm Max; Frequency - Self Resonant: 10MHz; Inductance: 33 µH; Inductance Frequency - Test: 100 kHz; Material - Core: Ferrite; Shielding: Shielded; Tolerance: ±20%; Type: Drum Core, Wirewound; Value: 33 µH
R1-R13 R15-R25 R28-R33 R35-R37 R39 R40 R43 R50-R52 R56-R66 R68 R70-R72 R75-R80 R90-R92 R95-R98 = RCS0805604RFKEA: RES SMD 604 OHM 1% 1/2W 0805; Manufacturer: Vishay Dale; Power (Watts): 0.5W, 1/2W; Resistance: 604 Ohms; Temperature Coefficient: ±100ppm/°C
R53 R93 R99 = ERJ-U6SFR10V: RES 0.1 OHM 1% 1/4W 0805; Manufacturer: Panasonic Electronic Components; Power (Watts): 0.25W, 1/4W; Resistance: 100 mOhms; Temperature Coefficient: ±150ppm/°C
S1 S2 = SS12D07VG4NSGAPA: Switch; Manufacturer_Name: C & K COMPONENTS
S3 = SK-13D08-G_5_E: Switch; Manufacturer_Name: C & K COMPONENTS; Manufacturer_Part_Number: SK-13D08-G 5 E
SW1 = SWITCH_6_4
TP1-TP6 TP8-TP15 = TP
U3 = HM538123
U4 U6 = 4558: Operation amp; Manufacturer_Name: Texas Instruments; Manufacturer_Part_Number: OPA2134UA
U5 = CXA1645: Video coder
U10 = 74HC257D,652: Integrated Circuit; Manufacturer_Name: Nexperia
U11 = HEF4066BT,653: Integrated Circuit; Manufacturer_Name: Nexperia
VC1 VC2 = TZB4P400AB10R00: Capacitor; Manufacturer_Name: Murata Electronics
Y1 Y2 = 12.000MHz_HC49_4H_30_50_-40+85_18pF_ATF: Crystal or Oscillator; Manufacturer_Name: EUROQUARTZ; Manufacturer_Part_Number: 12.000MHz HC49/4H/30/50/-40+85/18pF/ATF

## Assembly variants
Variant  2 of PCB_Project: all parts fitted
